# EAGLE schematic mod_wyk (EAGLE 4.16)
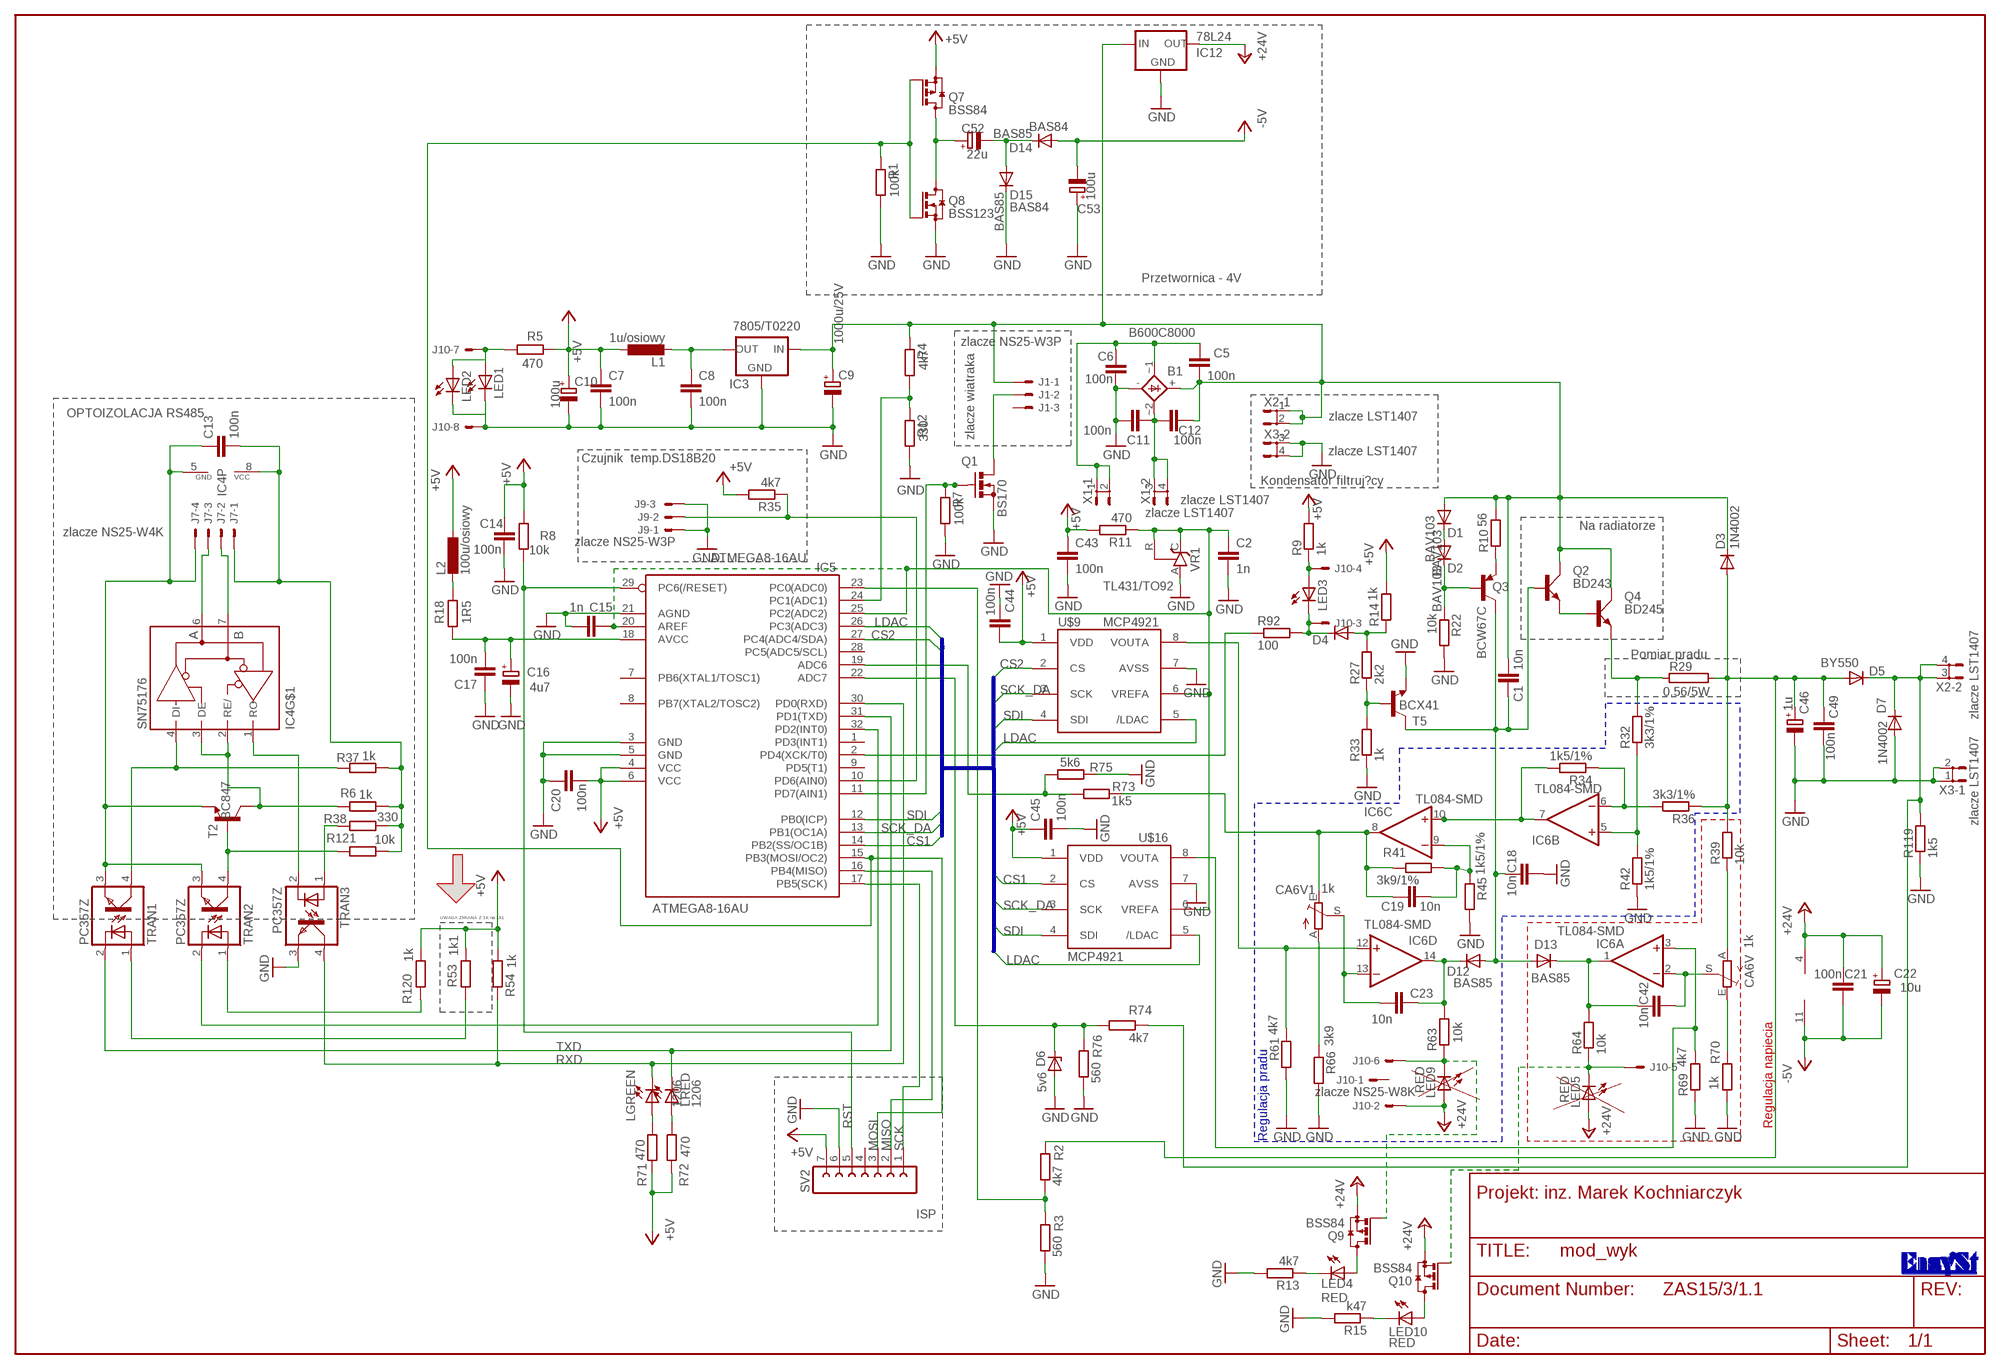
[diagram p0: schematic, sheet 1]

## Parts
B1  B600C8000  2KBB_R2  [2KBB_R2]
C1  10n  C-EUC0805  [C0805]
C2  1n  C-EUC0805  [C0805]
C5  100n  C-EUC0805  [C0805]
C6  100n  C-EUC0805  [C0805]
C7  100n  C-EUC0805  [C0805]
C8  100n  C-EUC0805  [C0805]
C9  1000u/25V  CPOL-EUTT5D11  [TT5D11]
C10  100u  CPOL-EUTT2D5  [TT2D5]
C11  100n  C-EUC0805  [C0805]
C12  100n  C-EUC0805  [C0805]
C13  100n  C-EUC0805  [C0805]
C14  100n  C-EUC0805  [C0805]
C15  1n  C-EUC0805  [C0805]
C16  4u7  CPOL-EUTT2D5  [TT2D5]
C17  100n  C-EUC0805  [C0805]
C18  10n  C-EUC0805  [C0805]
C19  10n  C-EUC0805  [C0805]
C20  100n  C-EUC0805  [C0805]
C21  100n  C-EUC0805  [C0805]
C22  10u  CPOL-EUTT2D5  [TT2D5]
C23  10n  C-EUC0805  [C0805]
C42  10n  C-EUC0805  [C0805]
C43  100n  C-EUC0805  [C0805]
C44  100n  C-EUC0805  [C0805]
C45  100n  C-EUC0805  [C0805]
C46  1u  CPOL-EUTT2D5  [TT2D5]
C49  100n  C-EUC0805  [C0805]
C52  22u  CPOL-EUTT2D5  [TT2D5]
C53  100u  CPOL-EUTT2D6  [TT2D6]
CA6V  1k  TRIM_EU-CA6H  [CA6H]
CA6V1  1k  TRIM_EU-CA6H  [CA6H]
D1  BAV103  DIODE-MINIMELF  [MINIMELF]
D2  BAV103  DIODE-MINIMELF  [MINIMELF]
D3  1N4002  DIODE-P1-10  [P1-10]
D4  DIODE-MINIMELF  [MINIMELF]
D5  BY550  DIODE-P6-15  [P6-15]
D6  5v6  ZENER-DIODESOT23  [SOT23]
D7  1N4002  DIODE-P1-10  [P1-10]
D12  BAS85  DIODE-MINIMELF  [MINIMELF]
D13  BAS85  DIODE-MINIMELF  [MINIMELF]
D14  BAS85  DIODE-MINIMELF  [MINIMELF]
D15  BAS85  DIODE-MINIMELF  [MINIMELF]
IC3  7805/T0220  78XXS  [78XXS]
IC4  SN75176  MAX481CSA  [SO08]
IC5  ATMEGA8-16AU  MEGA8-AI  [TQFP32-08]
IC6  TL084-SMD  TL084D  [SO14]
IC12  78L24  78LXX  [78LXX]
J1  zlacze NS25-W3P  22-27-2031-03  [6410-03]
J7  zlacze NS25-W4K  22-05-7048-04  [7395-04]
J9  zlacze NS25-W3P  22-27-2031-03  [6410-03]
J10  zlacze NS25-W8K  22-05-7088-08  [7395-08]
L1  1u/osiowy  L-EU0207/12  [0207/12]
L2  100u/osiowy  L-EU0207/10  [0207/10]
LED1  LED3MM  [LED3MM]
LED2  LED3MM  [LED3MM]
LED3  LED3MM  [LED3MM]
LED4  RED  LED3MM  [LED3MM]
LED5  RED  LED3MM  [LED3MM]
LED9  RED  LED3MM  [LED3MM]
LED10  RED  LED3MM  [LED3MM]
LGREEN  1206  LEDSMT1206  [1206]
LRED  1206  LEDSMT1206  [1206]
Q1  BS170  [SOT54E]
Q2  BD243  TIP41C  [TO220AV]
Q3  BCW67C  BCX71SMD  [SOT23]
Q4  BD245  TIP3055  [TOP3AV]
Q7  BSS84  [SOT23]
Q8  BSS123  [SOT23]
Q9  BSS84  [SOT23]
Q10  BSS84  [SOT23]
R1  100k  R-EU_R0805  [R0805]
R2  4k7  R-EU_R0805  [R0805]
R3  560  R-EU_R0805  [R0805]
R4  4k7  R-EU_R0805  [R0805]
R5  470  R-EU_R0805  [R0805]
R6  1k  R-EU_R0805  [R0805]
R7  100k  R-EU_M0805  [M0805]
R8  10k  R-EU_R0805  [R0805]
R9  1k  R-EU_R0805  [R0805]
R10  56  R-EU_0207/10  [0207/10]
R11  470  R-EU_R0805  [R0805]
R12  330  R-EU_R0805  [R0805]
R13  4k7  R-EU_R0805  [R0805]
R14  1k  R-EU_R0805  [R0805]
R15  k47  R-EU_R0805  [R0805]
R18  1R5  R-EU_R0805  [R0805]
R22  10k  R-EU_R0805  [R0805]
R27  2k2  R-EU_R0805  [R0805]
R29  0.56/5W  RKH208-8  [KH208-8]
R32  3k3/1%  R-EU_R0805  [R0805]
R33  1k  R-EU_R0805  [R0805]
R34  1k5/1%  R-EU_R0805  [R0805]
R35  4k7  R-EU_R0805  [R0805]
R36  3k3/1%  R-EU_R0805  [R0805]
R37  1k  R-EU_R0805  [R0805]
R38  330  R-EU_M0805  [M0805]
R39  10k  R-EU_R0805  [R0805]
R41  3k9/1%  R-EU_R0805  [R0805]
R42  1k5/1%  R-EU_R0805  [R0805]
R45  1k5/1%  R-EU_R0805  [R0805]
R53  1k1  R-EU_R0805  [R0805]
R54  1k  R-EU_R0805  [R0805]
R61  4k7  R-EU_R0805  [R0805]
R63  10k  R-EU_R0805  [R0805]
R64  10k  R-EU_R0805  [R0805]
R66  3k9  R-EU_R0805  [R0805]
R69  4k7  R-EU_R0805  [R0805]
R70  1k  R-EU_R0805  [R0805]
R71  470  R-EU_R0805  [R0805]
R72  470  R-EU_R0805  [R0805]
R73  1k5  R-EU_R0805  [R0805]
R74  4k7  R-EU_R0805  [R0805]
R75  5k6  R-EU_R0805  [R0805]
R76  560  R-EU_R0805  [R0805]
R92  100  R-EU_R0805  [R0805]
R119  1k5  R-EU_0207/7  [0207/7]
R120  1k  R-EU_R0805  [R0805]
R121  10k  R-EU_R0805  [R0805]
SV2  FE07-1  [FE07]
T2  BC847  BCX70SMD  [SOT23]
T5  BCX41  BCX70SMD  [SOT23]
TRAN1  PC357Z  [MFP4]
TRAN2  PC357Z  [MFP4]
TRAN3  PC357Z  [MFP4]
U$9  MCP4921  [SO-08]
U$16  MCP4921  [SO-08]
VR1  TL431/TO92  TL431CLP  [TO92-CLP]
X1  zlacze LST1407  SH5-2  [SH5-2]
X2  zlacze LST1407  SH5-2  [SH5-2]
X3  zlacze LST1407  SH5-2  [SH5-2]

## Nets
+5V: C7.1 C10.+ C14.1 C20.2 C43.1 C44.2 C45.1 IC5.4(VCC) IC5.6(VCC) L1.1 L2.1 Q7.2(S) R5.1 R8.2 R9.2 R11.2 R14.2 R35.2 R53.1 R54.1 R71.1 R72.1 R120.1 SV2.7 U$9.1(VDD) U$16.1(VDD)
+24V: C21.1 C22.+ IC6.4(P:V+) IC12.OUT J10.2 LED5.A LED9.A Q9.2(S) Q10.2(S)
-5V: C21.2 C22.- C53.- D14.A IC6.11(P:V-)
A: IC4.6(A) J7.3
ADC6: IC5.19(ADC6) R73.2 R75.2
ADC7: D6.3(C) IC5.22(ADC7) R74.1 R76.2
AVCC: C16.+ C17.2 IC5.18(AVCC) R18.2
B: IC4.7(B) J7.2
CS1: IC5.14(PB2(SS/OC1B)) U$16.2(CS)
CS2: IC5.27(PC4(ADC4/SDA)) U$9.2(CS)
GND: B1.- C2.2 C6.2 C7.2 C8.2 C9.- C10.- C11.1 C14.2 C15.1 C16.- C17.1 C18.2 C20.1 C43.2 C44.1 C45.2 C46.- C49.1 C53.+ D6.1(A) D7.A D15.C IC3.GND IC5.3(GND) IC5.5(GND) IC5.21(AGND) IC12.GND J9.1 J9.3 J10.8 LED1.K(C) LED2.K(C) Q1.S Q8.2(S) R1.2 R3.1 R7.2 R12.2 R13.2 R15.2 R22.2 R33.1 R42.1 R45.2 R61.1 R66.2 R69.1 R70.1 R75.1 R76.1 R119.1 SV2.6 T5.2(E) TRAN3.3(EMIT) U$9.7(AVSS) U$16.7(AVSS) VR1.A X3.1 X3.2 X3.3 X3.4
GND_RS485: C13.1 IC4.5(P:GND) J7.4 T2.2(E) TRAN1.3(EMIT) TRAN2.3(EMIT)
IOUT: IC6.12(D:+IN) R61.2 U$9.8(VOUTA)
LDAC: IC5.26(PC3(ADC3)) U$9.5(/LDAC) U$16.5(/LDAC)
MISO: IC5.16(PB4(MISO)) SV2.2
MOSI: IC5.15(PB3(MOSI/OC2)) Q7.1(G) Q8.1(G) R1.1 SV2.3
N$1: CA6V.A R39.1
N$2: IC6.6(B:-IN) R34.1 R36.2
N$3: C42.2 CA6V.S IC6.2(A:-IN)
N$4: IC6.5(B:+IN) R32.1 R42.2
N$5: IC6.7(B:OUT) IC6.10(C:+IN) R34.2
N$6: C23.1 CA6V1.S IC6.13(D:-IN)
N$7: C19.2 IC6.9(C:-IN) R41.2 R45.1
N$8: C19.1 CA6V1.E IC6.8(C:OUT) R41.1 R73.1
N$10: C1.1 C18.1 D12.A D13.A Q2.B Q3.3(C) T5.3(C)
N$11: R120.2 TRAN2.1(A)
N$12: IC5.32(PD2(INT0)) TRAN2.2(C)
N$14: CA6V.E R70.2
N$16: C23.2 D12.C IC6.14(D:OUT) R63.2
N$17: CA6V1.A R66.1
N$19: Q4.E R29.1 R32.2
N$22: D4.A R14.1 R27.2
N$23: D1.C D2.A
N$25: R27.1 R33.2 T5.1(B)
N$28: Q2.E Q4.B
N$31: LED4.A Q9.3(D)
N$33: C52.+ Q7.3(D) Q8.3(D)
N$34: IC4.4(DI) R37.2 TRAN1.4(COL)
N$35: IC5.10(PD6(AIN0)) J9.2 R35.1
N$36: D2.C Q3.1(B) R22.1
N$37: J10.6 LED9.K(C) Q9.1(G) R63.1
N$38: J10.5 LED5.K(C) Q10.1(G) R64.1
N$39: IC5.23(PC0(ADC0)) R2.1 R3.2
N$40: C46.+ C49.2 D3.A D5.A R2.2 R29.2 R36.1 R39.2
N$42: C52.- D14.C D15.A
N$43: L2.2 R18.1
N$44: R53.2 TRAN1.1(A)
N$45: IC4.1(RO) TRAN3.2(C)
N$47: IC5.24(PC1(ADC1)) R4.2 R12.1
N$54: R38.2 TRAN3.1(A)
N$55: R121.2 T2.1(B) TRAN2.4(COL)
N$56: C8.1 IC3.OUT L1.2
N$57: J10.7 LED1.A LED2.A R5.2
N$59: D5.C D7.C R74.2 R119.2 X2.3 X2.4
N$60: C42.1 D13.C IC6.1(A:OUT) R64.2
N$64: LRED.A R72.2
N$65: IC4.2(RE/) IC4.3(DE) R6.2 T2.3(C)
N$66: LGREEN.A R71.2
N$67: Q3.2(E) R10.1
N$68: B1.~2(AC2) C11.2 C12.1 X1.3 X1.4
N$69: B1.~1(AC1) C5.1 C6.1 X1.1 X1.2
N$100: D4.C J10.3 LED3.K(C) R92.2
N$112: J1.2 Q1.D
N$115: IC5.11(PD7(AIN1)) Q1.G R7.1
N$124: LED4.K(C) R13.1
N$126: LED10.A Q10.3(D)
N$128: LED10.K(C) R15.1
N$142: C2.1 C15.2 IC5.20(AREF) IC5.25(PC2(ADC2)) R11.1 U$9.6(VREFA) U$16.6(VREFA) VR1.C VR1.R
N$144: J10.4 LED3.A R9.1
RST: IC5.29(PC6(/RESET)) R8.1 SV2.5
RXD: IC5.30(PD0(RXD)) LGREEN.C R54.2 TRAN3.4(COL)
SCK: IC5.17(PB5(SCK)) SV2.1
SCK_DA: IC5.13(PB1(OC1A)) U$9.3(SCK) U$16.3(SCK)
SDI: IC5.12(PB0(ICP)) U$9.4(SDI) U$16.4(SDI)
TXD: IC5.31(PD1(TXD)) LRED.C TRAN1.2(C)
V+: B1.+ C1.2 C5.2 C9.+ C12.2 D1.A D3.C IC3.IN IC12.IN J1.1 Q2.C Q4.C R4.1 R10.2 X2.1 X2.2
VCC_RS485: C13.2 IC4.8(P:VCC) J7.1 R6.1 R37.1 R38.1 R121.1
VOUT: IC6.3(A:+IN) R69.2 U$16.8(VOUTA)
ZAS_ON_OFF: IC5.2(PD4(XCK/T0)) R92.1
Unconnected: IC5.1(PD3(INT1)) IC5.7(PB6(XTAL1/TOSC1)) IC5.8(PB7(XTAL2/TOSC2)) IC5.9(PD5(T1)) IC5.28(PC5(ADC5/SCL)) J1.3 J10.1 SV2.4

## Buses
CS1,CS2,SCK_DA,SDI,LDAC

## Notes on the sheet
- BAS84
- BAS84
- Przetwornica - 4V
- OPTOIZOLACJA RS485
- zlacze wiatraka
- Czujnik  temp.DS18B20
- Kondensator filtruj?cy
- Na radiatorze
- BAV103
- Pomiar pradu
- ATMEGA8-16AU
- UWAGA ZMIANA Z 1K na 1k1
- Regulacja napiecia
- Regulacja pradu
- Projekt: inz. Marek Kochniarczyk
- ISP
- D:/logo_ensyst_1bit.bmp
- ZAS15/3/1.1

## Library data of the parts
B1 = rectifier:2KBB_R2
C1 C2 C5-C8 C11-C15 C17-C21 C23 C42-C45 C49 = rcl:C-EU: CAPACITOR, European symbol
C9 C10 C16 C22 C46 C52 C53 = rcl:CPOL-EU: POLARIZED CAPACITOR, European symbol
CA6V CA6V1 = pot:TRIM_EU-: POTENTIOMETER
D1-D5 D7 D12-D15 = diode:DIODE-: DIODE
D6 = diode:ZENER-DIODE: Z-Diode
IC3 = v-reg:78XXS: VOLTAGE REGULATOR
IC4 = maxim:MAX481CSA: RS485 TRANSEIVER
IC5 = atmel:MEGA8: MICROCONTROLLER 8 Kbytes FLASH 1 kbytes SRAM 512 bytes EEPROM USART 6-channel 10 bit ADC 2-channel 8 bit ADC Source: avr.lbr
IC6 = linear:TL084: OP AMP
IC12 = v-reg:78LXX: VOLTAGE REGULATOR
J1 J9 = con-molex:22-?-03: CONNECTOR wire to board 2.54 mm (.1 inch) pitch header
J7 = con-molex:22-?-04: CONNECTOR wire to board 2.54 mm (.1 inch) pitch header
J10 = con-molex:22-?-08: CONNECTOR wire to board 2.54 mm (.1 inch) pitch header
L1 L2 = rcl:L-EU: INDUCTOR, European symbol
LED1-LED5 LED9 LED10 LGREEN LRED = led:LED: LED
Q1 = transistor-small-signal:BS170: N-CHANNEL MOS FET
Q2 = transistor-power:TIP41C: NPN TRANSISTOR
Q3 = transistor-pnp:BCX71SMD: PNP Transistor
Q4 = transistor-power:TIP3055: NPN TRANSISTOR
Q7 Q9 Q10 = transistor-small-signal:BSS84: P-CHANNEL MOS FET
Q8 = transistor-small-signal:BSS123: N-CHANNEL MOS FET
R1-R15 R18 R22 R27 R32-R39 R41 R42 R45 R53 R54 R61 R63 R64 R66 R69-R76 R92 R119-R121 = rcl:R-EU_: RESISTOR, European symbol
R29 = resistor-power:R: Power Resitor
SV2 = con-lsta:FE07-1: FEMALE HEADER
T2 T5 = transistor:BCX70SMD: NPN TRANSISTOR
TRAN1-TRAN3 = optocoupler:PC357Z
U$9 U$16 = microchip:MCP4921
VR1 = v-reg:TL431CLP: VOLTAGE REGULATOR
X1-X3 = con-rib:SH5-2: RIBBON CABLE CONNECTOR Flachstecker / Faston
